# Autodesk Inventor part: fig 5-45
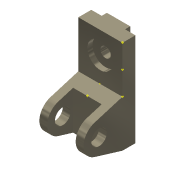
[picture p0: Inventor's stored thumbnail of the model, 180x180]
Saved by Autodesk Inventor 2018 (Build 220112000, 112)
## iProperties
Shininess: 65.0
Angle Display Precision: 2
Document Length Units: 11269
Document Angle Units: 11279
Document Time Units: 11290
Document Mass Units: 11283
Document Length Units Precision: 3
Document Angle Units Precision: 2
Created: 2001-11
Part Number: fig 5-45
Document SubType Name: Modeling
Designer: Renu Muthoo
Density: 1 g/cm^3
Material: Generic
Appearance: Metal-Titanium (Polished)
Density: 0.0
Volumn: 0.0
Area: 0.0
PropertySet Name: Model Information
Control State: 0
Master: False
Checked Out: False
Author: Renu Muthoo
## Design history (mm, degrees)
node "Sketch1"
sketch "Sketch2"
  geometry: L1 (33.257, 104.664)-(33.257, -75.336); L2 (33.257, -75.336)-(8.257, -75.336); L3 (8.257, -75.336)-(-45.451, -59.045); L4 (-45.451, -1.628)-(8.257, 14.664); L5 (8.257, 14.664)-(8.257, 104.664); L6 (8.257, 104.664)-(33.257, 104.664); C1 r 15 at (-36.743, -30.336); A1 r 30 centre (-36.743, -30.336) between (-45.451, -1.628) and (-45.451, -59.045)
  constraints: 12 end point, 2 centre point, 2 equal length, 2 parallel, 2 point on circle, 2 tangent, 1 coincident, 1 perpendicular, 1 vertical
  dimensions: "d0" = 180 distance of L1.start L1.end; "d1" = 30 radius of A1; "d2" = 25 distance of L5.end L1.start; "d3" = 45 distance from line of L2 A1.centre; "d4" = 70 distance from line of L1 A1.centre; "d5" = 30 diameter of C1
extrude "Extrusion1" new body sketch "Sketch2" distance "d6" = 85; taper "d7" = 0 deg
workplane "Work Plane1"
sketch "Sketch3"
  geometry: L1 (15, 62.364)-(70, 62.364); L2 (70, 62.364)-(70, -52.386); L3 (70, -52.386)-(15, -52.386); L4 (15, -52.386)-(15, 62.364); L5 (0, -45)-(0, -28.708) reference
  constraints: 8 end point, 2 parallel, 1 horizontal, 1 perpendicular
  dimensions: "d8" = 55 distance of L1.start L1.end; "d9" = 15 distance between parallel lines of L5 L4
extrude "Extrusion2" cut sketch "Sketch3" distance "d10" = 50; taper "d11" = 0 deg
sketch "Sketch4"
  geometry: L1 (0, 25)-(85, 25) reference; L2 (0, 0)-(0, 25) reference; L3 (20, 25)-(65, 25); L4 (65, 25)-(65, 35); L5 (65, 35)-(20, 35); L6 (20, 35)-(20, 25)
  constraints: 8 end point, 2 parallel, 1 horizontal, 1 perpendicular, 1 point on line
  dimensions: "d12" = 45 distance of L4.end L5.end; "d13" = 10 distance of L3.end L4.end; "d14" = 20 distance between parallel lines of L2 L6
extrude "Extrusion3" join sketch "Sketch4" stored distance "d15" = 50; taper "d16" = 0 deg
sketch "Sketch5"
  geometry: L1 (85, 0)-(85, 90) reference; L2 (0, 90)-(85, 90) reference; 1 further point
  dimensions: "d17" = 42 distance from line of L2 point (42.5, 48); "d18" = 42.5 distance from line of L1 point (42.5, 48)
hole "Hole1" sketch "Sketch5" at (42.5, 48) diameter "d19" = 20; stored, may be unused: countersink angle "d23" = 82 deg, drill point angle "d25" = 118 deg; dims "d20" = 6, "d21" = 50, "d22" = 10, "d24" = 8
workpoint "Work Point1"
workpoint "Work Point2"
workpoint "Work Point3"
workpoint "Work Point4"
workpoint "Work Point5"
body "Solid1"
